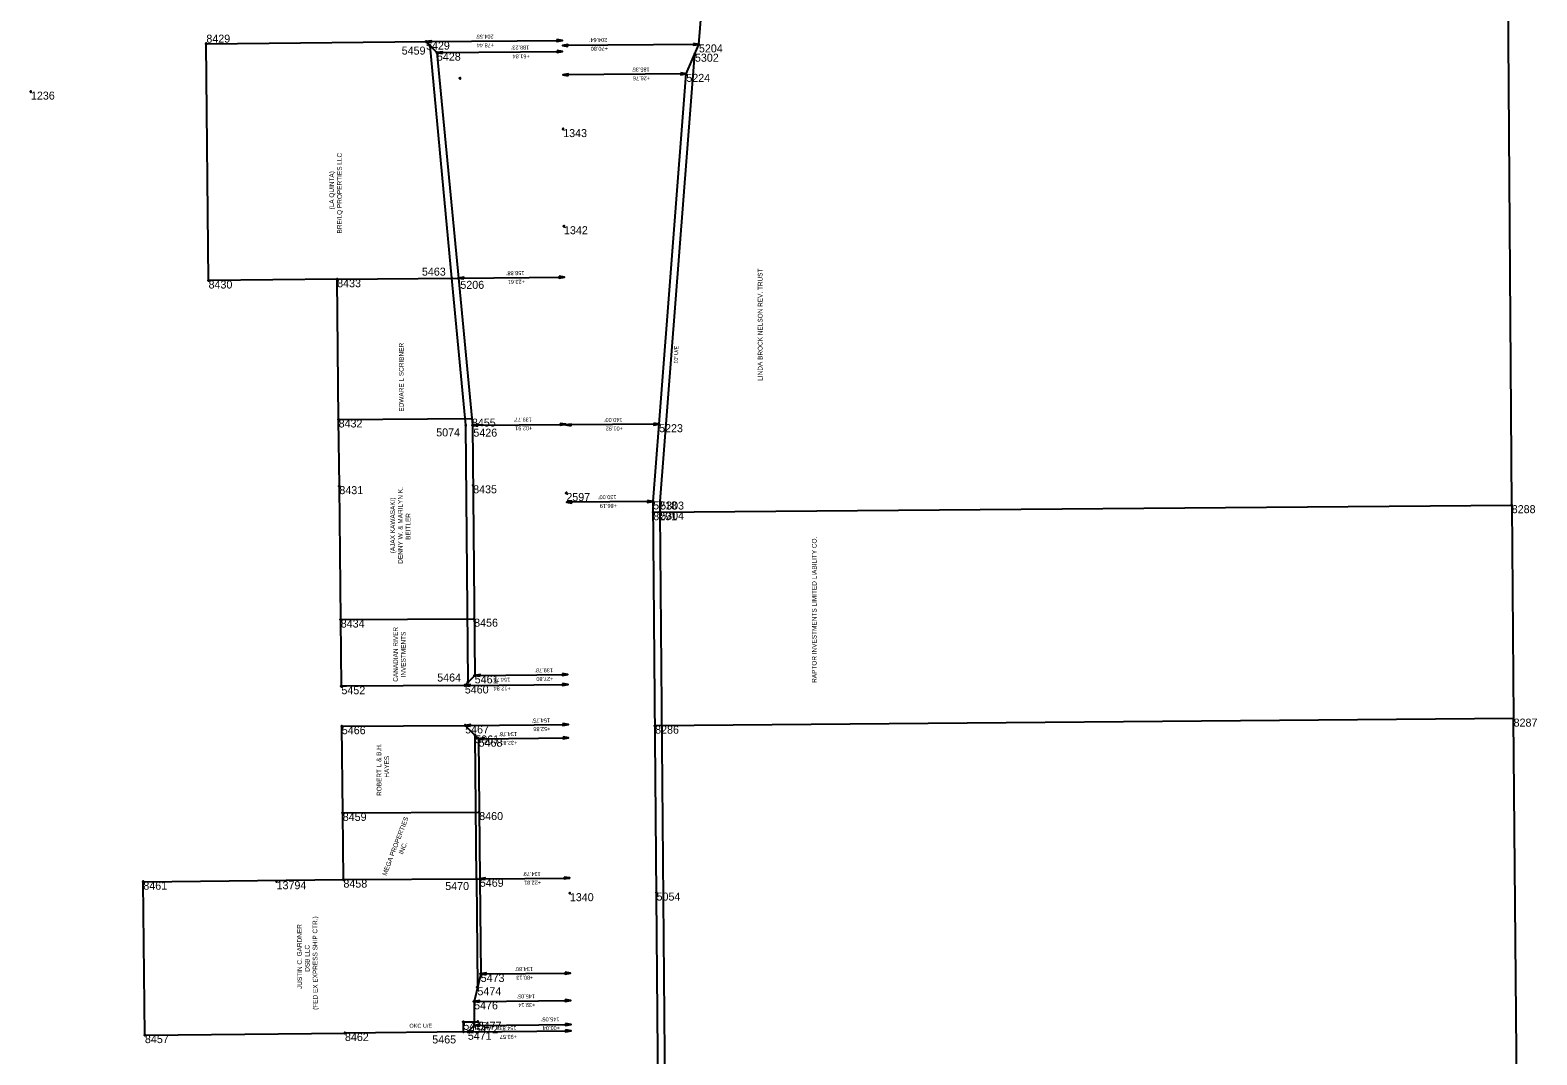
# Model space of a CAD drawing. Extents: x 2145146 to 2158053, y 137507 to 150829.
# Drawn here: x 2150050 to 2152309, y 138777 to 140313 of the extents above; entities that cross this region are included whole.
import ezdxf

# ---------------------------------------------------------------- set-up
doc = ezdxf.new("R2010")
doc.units = 0
for name, color, linetype in [('ALIGN_Cogo Points', 7, 'Continuous'), ('ALIGN_ROW Dimension', 7, 'Continuous'), ('ALIGN_ROW Line', 7, 'Continuous'), ('PLSS_Easement', 7, 'Continuous'), ('PLSS_Property Line', 7, 'Continuous'), ('PLSS_Text', 7, 'Continuous'), ('PLSS_Text_TURNED OFF', 7, 'Continuous')]:
    doc.layers.add(name, color=color, linetype=linetype)

# ---------------------------------------------------------------- blocks, each defined once
blk = doc.blocks.new('Arrowhd')
at = {"layer": 'PLSS_Property Line'}
blk.add_lwpolyline([(0.125, -0.021), (0.125, 0.021), (0, 0)], close=True, dxfattribs=at)

msp = doc.modelspace()

# ---------------------------------------------------------------- linework, layer by layer
at = {"layer": 'ALIGN_Cogo Points'}
for points in [[(2150314.4, 140292.8), (2150314.4, 140294), (2150314.4, 140292.8), (2150313.2, 140292.8), (2150314.4, 140292.8), (2150314.4, 140291.6), (2150314.4, 140292.8), (2150315.6, 140292.8)], [(2150643.8, 140296), (2150643.8, 140297.2), (2150643.8, 140296), (2150642.6, 140296), (2150643.8, 140296), (2150643.8, 140294.8), (2150643.8, 140296), (2150645, 140296)], [(2150649.8, 140289.9), (2150649.8, 140291.1), (2150649.8, 140289.9), (2150648.6, 140289.9), (2150649.8, 140289.9), (2150649.8, 140288.7), (2150649.8, 140289.9), (2150651, 140289.9)], [(2151053, 140291.9), (2151053, 140293.1), (2151053, 140291.9), (2151051.8, 140291.9), (2151053, 140291.9), (2151053, 140290.7), (2151053, 140291.9), (2151054.2, 140291.9)], [(2150660.2, 140279.5), (2150660.2, 140280.7), (2150660.2, 140279.5), (2150659, 140279.5), (2150660.2, 140279.5), (2150660.2, 140278.3), (2150660.2, 140279.5), (2150661.4, 140279.5)], [(2151047, 140277.9), (2151047, 140279.1), (2151047, 140277.9), (2151045.8, 140277.9), (2151047, 140277.9), (2151047, 140276.7), (2151047, 140277.9), (2151048.2, 140277.9)], [(2150694.9, 140241.2), (2150694.9, 140242.4), (2150694.9, 140241.2), (2150693.7, 140241.2), (2150694.9, 140241.2), (2150694.9, 140240), (2150694.9, 140241.2), (2150696.1, 140241.2)], [(2151034.1, 140247.7), (2151034.1, 140248.9), (2151034.1, 140247.7), (2151032.9, 140247.7), (2151034.1, 140247.7), (2151034.1, 140246.5), (2151034.1, 140247.7), (2151035.3, 140247.7)], [(2150051.5, 140221.1), (2150051.5, 140222.3), (2150051.5, 140221.1), (2150050.3, 140221.1), (2150051.5, 140221.1), (2150051.5, 140219.9), (2150051.5, 140221.1), (2150052.7, 140221.1)], [(2150849.5, 140164.9), (2150849.5, 140166.1), (2150849.5, 140164.9), (2150848.3, 140164.9), (2150849.5, 140164.9), (2150849.5, 140163.7), (2150849.5, 140164.9), (2150850.7, 140164.9)], [(2150850.7, 140019.3), (2150850.7, 140020.5), (2150850.7, 140019.3), (2150849.5, 140019.3), (2150850.7, 140019.3), (2150850.7, 140018.1), (2150850.7, 140019.3), (2150851.9, 140019.3)], [(2150317.8, 139937.9), (2150317.8, 139939.1), (2150317.8, 139937.9), (2150316.6, 139937.9), (2150317.8, 139937.9), (2150317.8, 139936.7), (2150317.8, 139937.9), (2150319, 139937.9)], [(2150510.6, 139939.8), (2150510.6, 139941), (2150510.6, 139939.8), (2150509.4, 139939.8), (2150510.6, 139939.8), (2150510.6, 139938.6), (2150510.6, 139939.8), (2150511.8, 139939.8)], [(2150682.5, 139941.4), (2150682.5, 139942.6), (2150682.5, 139941.4), (2150681.3, 139941.4), (2150682.5, 139941.4), (2150682.5, 139940.2), (2150682.5, 139941.4), (2150683.7, 139941.4)], [(2150692.5, 139941.5), (2150692.5, 139942.7), (2150692.5, 139941.5), (2150691.3, 139941.5), (2150692.5, 139941.5), (2150692.5, 139940.3), (2150692.5, 139941.5), (2150693.7, 139941.5)], [(2150512.8, 139729.6), (2150512.8, 139730.8), (2150512.8, 139729.6), (2150511.6, 139729.6), (2150512.8, 139729.6), (2150512.8, 139728.4), (2150512.8, 139729.6), (2150514, 139729.6)], [(2150703.6, 139720.9), (2150703.6, 139722.1), (2150703.6, 139720.9), (2150702.4, 139720.9), (2150703.6, 139720.9), (2150703.6, 139719.7), (2150703.6, 139720.9), (2150704.8, 139720.9)], [(2150712.6, 139730.9), (2150712.6, 139732.1), (2150712.6, 139730.9), (2150711.4, 139730.9), (2150712.6, 139730.9), (2150712.6, 139729.7), (2150712.6, 139730.9), (2150713.8, 139730.9)], [(2150713.6, 139721), (2150713.6, 139722.2), (2150713.6, 139721), (2150712.4, 139721), (2150713.6, 139721), (2150713.6, 139719.8), (2150713.6, 139721), (2150714.8, 139721)], [(2150993.3, 139722.5), (2150993.3, 139723.7), (2150993.3, 139722.5), (2150992.1, 139722.5), (2150993.3, 139722.5), (2150993.3, 139721.3), (2150993.3, 139722.5), (2150994.5, 139722.5)], [(2150513.9, 139629.6), (2150513.9, 139630.8), (2150513.9, 139629.6), (2150512.7, 139629.6), (2150513.9, 139629.6), (2150513.9, 139628.4), (2150513.9, 139629.6), (2150515.1, 139629.6)], [(2150714.5, 139630.9), (2150714.5, 139632.1), (2150714.5, 139630.9), (2150713.3, 139630.9), (2150714.5, 139630.9), (2150714.5, 139629.7), (2150714.5, 139630.9), (2150715.7, 139630.9)], [(2150854.2, 139619.3), (2150854.2, 139620.5), (2150854.2, 139619.3), (2150853, 139619.3), (2150854.2, 139619.3), (2150854.2, 139618.1), (2150854.2, 139619.3), (2150855.4, 139619.3)], [(2150984.4, 139606.7), (2150984.4, 139607.9), (2150984.4, 139606.7), (2150983.2, 139606.7), (2150984.4, 139606.7), (2150984.4, 139605.5), (2150984.4, 139606.7), (2150985.6, 139606.7)], [(2150994.9, 139606.5), (2150994.9, 139607.7), (2150994.9, 139606.5), (2150993.7, 139606.5), (2150994.9, 139606.5), (2150994.9, 139605.3), (2150994.9, 139606.5), (2150996.1, 139606.5)], [(2150984.5, 139590.5), (2150984.5, 139591.7), (2150984.5, 139590.5), (2150983.3, 139590.5), (2150984.5, 139590.5), (2150984.5, 139589.3), (2150984.5, 139590.5), (2150985.7, 139590.5)], [(2150995, 139591.4), (2150995, 139592.6), (2150995, 139591.4), (2150993.8, 139591.4), (2150995, 139591.4), (2150995, 139590.2), (2150995, 139591.4), (2150996.2, 139591.4)], [(2152271.6, 139601.1), (2152271.6, 139602.3), (2152271.6, 139601.1), (2152270.4, 139601.1), (2152271.6, 139601.1), (2152271.6, 139599.9), (2152271.6, 139601.1), (2152272.8, 139601.1)], [(2150516, 139429.6), (2150516, 139430.8), (2150516, 139429.6), (2150514.8, 139429.6), (2150516, 139429.6), (2150516, 139428.4), (2150516, 139429.6), (2150517.2, 139429.6)], [(2150716, 139430.9), (2150716, 139432.1), (2150716, 139430.9), (2150714.8, 139430.9), (2150716, 139430.9), (2150716, 139429.7), (2150716, 139430.9), (2150717.2, 139430.9)], [(2150706.9, 139335.8), (2150706.9, 139337), (2150706.9, 139335.8), (2150705.7, 139335.8), (2150706.9, 139335.8), (2150706.9, 139334.6), (2150706.9, 139335.8), (2150708.1, 139335.8)], [(2150716.8, 139345.9), (2150716.8, 139347.1), (2150716.8, 139345.9), (2150715.6, 139345.9), (2150716.8, 139345.9), (2150716.8, 139344.7), (2150716.8, 139345.9), (2150718, 139345.9)], [(2150517, 139329.6), (2150517, 139330.8), (2150517, 139329.6), (2150515.8, 139329.6), (2150517, 139329.6), (2150517, 139328.4), (2150517, 139329.6), (2150518.2, 139329.6)], [(2150702, 139330.8), (2150702, 139332), (2150702, 139330.8), (2150700.8, 139330.8), (2150702, 139330.8), (2150702, 139329.6), (2150702, 139330.8), (2150703.2, 139330.8)], [(2150517.6, 139269.7), (2150517.6, 139270.9), (2150517.6, 139269.7), (2150516.4, 139269.7), (2150517.6, 139269.7), (2150517.6, 139268.5), (2150517.6, 139269.7), (2150518.8, 139269.7)], [(2150702.5, 139270.9), (2150702.5, 139272.1), (2150702.5, 139270.9), (2150701.3, 139270.9), (2150702.5, 139270.9), (2150702.5, 139269.7), (2150702.5, 139270.9), (2150703.7, 139270.9)], [(2150987.3, 139270.5), (2150987.3, 139271.7), (2150987.3, 139270.5), (2150986.1, 139270.5), (2150987.3, 139270.5), (2150987.3, 139269.3), (2150987.3, 139270.5), (2150988.5, 139270.5)], [(2152274.4, 139281.1), (2152274.4, 139282.3), (2152274.4, 139281.1), (2152273.2, 139281.1), (2152274.4, 139281.1), (2152274.4, 139279.9), (2152274.4, 139281.1), (2152275.6, 139281.1)], [(2150717.7, 139255.9), (2150717.7, 139257.1), (2150717.7, 139255.9), (2150716.5, 139255.9), (2150717.7, 139255.9), (2150717.7, 139254.7), (2150717.7, 139255.9), (2150718.9, 139255.9)], [(2150722.7, 139251), (2150722.7, 139252.2), (2150722.7, 139251), (2150721.5, 139251), (2150722.7, 139251), (2150722.7, 139249.8), (2150722.7, 139251), (2150723.9, 139251)], [(2150519, 139139.7), (2150519, 139140.9), (2150519, 139139.7), (2150517.8, 139139.7), (2150519, 139139.7), (2150519, 139138.5), (2150519, 139139.7), (2150520.2, 139139.7)], [(2150723.6, 139141), (2150723.6, 139142.2), (2150723.6, 139141), (2150722.4, 139141), (2150723.6, 139141), (2150723.6, 139139.8), (2150723.6, 139141), (2150724.8, 139141)], [(2150520, 139039.7), (2150520, 139040.9), (2150520, 139039.7), (2150518.8, 139039.7), (2150520, 139039.7), (2150520, 139038.5), (2150520, 139039.7), (2150521.2, 139039.7)], [(2150719.5, 139041), (2150719.5, 139042.2), (2150719.5, 139041), (2150718.3, 139041), (2150719.5, 139041), (2150719.5, 139039.8), (2150719.5, 139041), (2150720.7, 139041)], [(2150724.5, 139041), (2150724.5, 139042.2), (2150724.5, 139041), (2150723.3, 139041), (2150724.5, 139041), (2150724.5, 139039.8), (2150724.5, 139041), (2150725.7, 139041)], [(2150220, 139036.6), (2150220, 139037.8), (2150220, 139036.6), (2150218.8, 139036.6), (2150220, 139036.6), (2150220, 139035.4), (2150220, 139036.6), (2150221.2, 139036.6)], [(2150419.8, 139037.3), (2150419.8, 139038.5), (2150419.8, 139037.3), (2150418.6, 139037.3), (2150419.8, 139037.3), (2150419.8, 139036.1), (2150419.8, 139037.3), (2150421, 139037.3)], [(2150859.5, 139019.4), (2150859.5, 139020.6), (2150859.5, 139019.4), (2150858.3, 139019.4), (2150859.5, 139019.4), (2150859.5, 139018.2), (2150859.5, 139019.4), (2150860.7, 139019.4)], [(2150989.5, 139020.3), (2150989.5, 139021.5), (2150989.5, 139020.3), (2150988.3, 139020.3), (2150989.5, 139020.3), (2150989.5, 139019.1), (2150989.5, 139020.3), (2150990.7, 139020.3)], [(2150725.8, 138898.3), (2150725.8, 138899.5), (2150725.8, 138898.3), (2150724.6, 138898.3), (2150725.8, 138898.3), (2150725.8, 138897.1), (2150725.8, 138898.3), (2150727, 138898.3)], [(2150720.9, 138878.3), (2150720.9, 138879.5), (2150720.9, 138878.3), (2150719.7, 138878.3), (2150720.9, 138878.3), (2150720.9, 138877.1), (2150720.9, 138878.3), (2150722.1, 138878.3)], [(2150715.9, 138857.2), (2150715.9, 138858.4), (2150715.9, 138857.2), (2150714.7, 138857.2), (2150715.9, 138857.2), (2150715.9, 138856), (2150715.9, 138857.2), (2150717.1, 138857.2)], [(2150699.8, 138826.5), (2150699.8, 138827.7), (2150699.8, 138826.5), (2150698.6, 138826.5), (2150699.8, 138826.5), (2150699.8, 138825.3), (2150699.8, 138826.5), (2150701, 138826.5)], [(2150716.2, 138821.1), (2150716.2, 138822.3), (2150716.2, 138821.1), (2150715, 138821.1), (2150716.2, 138821.1), (2150716.2, 138819.9), (2150716.2, 138821.1), (2150717.4, 138821.1)], [(2150721.3, 138826.7), (2150721.3, 138827.9), (2150721.3, 138826.7), (2150720.1, 138826.7), (2150721.3, 138826.7), (2150721.3, 138825.5), (2150721.3, 138826.7), (2150722.5, 138826.7)], [(2150222.4, 138806.6), (2150222.4, 138807.8), (2150222.4, 138806.6), (2150221.2, 138806.6), (2150222.4, 138806.6), (2150222.4, 138805.4), (2150222.4, 138806.6), (2150223.6, 138806.6)], [(2150522.3, 138809.7), (2150522.3, 138810.9), (2150522.3, 138809.7), (2150521.1, 138809.7), (2150522.3, 138809.7), (2150522.3, 138808.5), (2150522.3, 138809.7), (2150523.5, 138809.7)], [(2150700, 138811.5), (2150700, 138812.7), (2150700, 138811.5), (2150698.8, 138811.5), (2150700, 138811.5), (2150700, 138810.3), (2150700, 138811.5), (2150701.2, 138811.5)], [(2150706.5, 138811.6), (2150706.5, 138812.8), (2150706.5, 138811.6), (2150705.3, 138811.6), (2150706.5, 138811.6), (2150706.5, 138810.4), (2150706.5, 138811.6), (2150707.7, 138811.6)]]:
    msp.add_lwpolyline(points, dxfattribs=at)
at = {"layer": 'ALIGN_ROW Dimension'}
for points in [[(2150643.8, 140296), (2150848.3, 140297.7)], [(2151053, 140291.9), (2150848.4, 140290.1)], [(2150660.2, 140279.5), (2150848.5, 140281.2)], [(2151034.1, 140247.7), (2150848.8, 140246.1)], [(2150692.5, 139941.5), (2150851.4, 139942.9)], [(2150713.6, 139721), (2150853.3, 139722.2)], [(2150993.3, 139722.5), (2150853.4, 139721.3)], [(2150984.4, 139606.6), (2150854.4, 139605.5)], [(2150716.8, 139345.9), (2150856.6, 139347.1)], [(2150702, 139330.8), (2150856.8, 139332.2)], [(2150702.5, 139270.9), (2150857.3, 139272.2)], [(2150722.7, 139251), (2150857.5, 139252.2)], [(2150724.5, 139041), (2150859.3, 139042.1)], [(2150725.8, 138898.3), (2150860.5, 138899.5)], [(2150715.9, 138857.2), (2150860.9, 138858.5)], [(2150716.2, 138821.1), (2150861.2, 138822.4)], [(2150706.5, 138811.6), (2150861.3, 138812.9)]]:
    msp.add_lwpolyline(points, dxfattribs=at)
at = {"layer": 'ALIGN_ROW Line'}
for points in [[(2151467.6, 137757.4), (2151467.4, 137784.4), (2151080.4, 137781.2), (2151054.8, 137833.2), (2151025, 138270.8), (2151014.8, 138420.9), (2151013.1, 138620.9), (2151002.2, 138720.8), (2150992.1, 138720.5), (2150984.4, 139606.7), (2150993.3, 139722.5), (2151034.1, 140247.7), (2151053, 140291.9), (2151058.3, 140359.7), (2151125.2, 141214)], [(2150314.4, 140292.8), (2150643.8, 140296), (2150660.2, 140279.5), (2150692.5, 139941.5), (2150713.6, 139721), (2150716.8, 139345.9), (2150702, 139330.8), (2150517, 139329.6)], [(2150517.6, 139269.7), (2150702.5, 139270.9), (2150722.7, 139251), (2150724.5, 139041), (2150725.8, 138898.3), (2150715.9, 138857.2), (2150716.2, 138821.1), (2150706.5, 138811.6), (2150522.3, 138809.7)]]:
    msp.add_lwpolyline(points, dxfattribs=at)
at = {"layer": 'PLSS_Easement'}
for points in [[(2150706.9, 139335.8), (2150703.6, 139720.9), (2150682.5, 139941.4), (2150649.8, 140289.9)], [(2150995, 139591.4), (2150994.9, 139606.5), (2151047, 140277.9)], [(2151002.2, 138720.8), (2150995, 139590.2)], [(2150719.5, 139041), (2150717.7, 139255.9)], [(2150719.5, 139041), (2150720.9, 138878.3)], [(2150700, 138811.5), (2150699.8, 138826.5), (2150721.3, 138826.7)]]:
    msp.add_lwpolyline(points, dxfattribs=at)
at = {"layer": 'PLSS_Property Line'}
for points in [[(2152271.6, 139601.1), (2152266.1, 140368.7), (2151058.3, 140359.7)], [(2150510.6, 139939.8), (2150317.8, 139937.9), (2150314.4, 140292.8)], [(2150512.8, 139729.6), (2150510.6, 139939.8), (2150692.5, 139941.5)], [(2150516, 139429.6), (2150513.9, 139629.6), (2150512.8, 139729.6), (2150712.6, 139730.9)], [(2150984.5, 139590.5), (2152271.6, 139601.1), (2152274.4, 139281.1)], [(2150517, 139329.6), (2150516, 139429.6), (2150716, 139430.9)], [(2150519, 139139.7), (2150517.6, 139269.7)], [(2152283.1, 138281.1), (2152274.4, 139281.1), (2150987.3, 139270.5)], [(2150520, 139039.7), (2150519, 139139.7), (2150723.6, 139141)], [(2150222.4, 138806.6), (2150220, 139036.6), (2150520, 139039.7), (2150724.5, 139041)], [(2150222.4, 138806.6), (2150522.3, 138809.7)]]:
    msp.add_lwpolyline(points, dxfattribs=at)

# ---------------------------------------------------------------- block references
at = {"layer": 'ALIGN_ROW Dimension', "yscale": 65}
for p, xscale, rotation in [((2150643.7, 140296), 65.00000000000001, 0.7805293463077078), ((2150848.2, 140297.8), 65, 180), ((2150848.4, 140290.1), 65.00000000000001, 0.780529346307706), ((2151053, 140291.9), 65, 180), ((2150660.2, 140279.5), 65.00000000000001, 0.7805293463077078), ((2150848.4, 140281.2), 65, 180), ((2150848.8, 140246.1), 65.00000000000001, 0.7805293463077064), ((2151034.1, 140247.7), 65, 180), ((2150692.5, 139941.5), 65.00000000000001, 0.7805293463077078), ((2150851.4, 139943), 65, 180), ((2150713.6, 139721), 65.00000000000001, 0.7805293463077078), ((2150853.3, 139722.3), 65, 180), ((2150853.4, 139721.3), 65.00000000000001, 0.7805293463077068), ((2150993.3, 139722.5), 65, 180), ((2150854.4, 139605.5), 65.00000000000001, 0.7805293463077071), ((2150984, 139606.7), 65, 180), ((2150716.8, 139345.9), 65.00000000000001, 0.7805293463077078), ((2150856.6, 139347.2), 65, 180), ((2150702, 139330.9), 65.00000000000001, 0.7805293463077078), ((2150856.7, 139332.2), 65, 180), ((2150702.5, 139270.8), 65.00000000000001, 0.7805293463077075), ((2150857.2, 139272.2), 65, 180), ((2150722.7, 139251), 65.00000000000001, 0.7805293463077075), ((2150857.4, 139252.2), 65, 180), ((2150724.6, 139041), 65.00000000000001, 0.7805293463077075), ((2150859.2, 139042.2), 65, 180), ((2150725.8, 138898.3), 65.00000000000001, 0.7805293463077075), ((2150860.5, 138899.5), 65, 180), ((2150715.9, 138857.2), 65.00000000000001, 0.7805293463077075), ((2150860.8, 138858.5), 65, 180), ((2150716.2, 138821.1), 65.00000000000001, 0.7805293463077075), ((2150861.2, 138822.4), 65, 180), ((2150706.5, 138811.6), 65.00000000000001, 0.7805293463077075), ((2150861.2, 138813), 65, 180)]:
    msp.add_blockref('Arrowhd', p, dxfattribs=dict(at, xscale=xscale, rotation=rotation))

# ---------------------------------------------------------------- texts
at = {"layer": 'ALIGN_Cogo Points'}
for s, p in [('8429', (2150314.5, 140294.5)), ('5459', (2150607.4, 140276.6)), ('5429', (2150643.8, 140284)), ('5204', (2151053, 140279.9)), ('5428', (2150660.2, 140267.5)), ('5302', (2151047, 140265.9)), ('5224', (2151034.1, 140235.7)), ('1236', (2150051.5, 140209.1)), ('1343', (2150849.5, 140152.9)), ('1342', (2150850.7, 140007.3)), ('5463', (2150637.7, 139945.2)), ('8430', (2150317.8, 139925.9)), ('8433', (2150510.6, 139927.8)), ('5206', (2150695.3, 139925.4)), ('8432', (2150512.8, 139717.6)), ('8455', (2150712.6, 139718.9)), ('5223', (2150993.3, 139710.5)), ('5074', (2150659.1, 139704.2)), ('5426', (2150714.8, 139703.8)), ('8431', (2150513.9, 139617.6)), ('8435', (2150714.5, 139618.9)), ('2597', (2150854.2, 139607.3)), ('5218', (2150984.4, 139594.7)), ('5303', (2150994.9, 139594.5)), ('8291', (2150984.5, 139578.5)), ('5304', (2150995, 139579.4)), ('8288', (2152271.6, 139589.1)), ('8434', (2150516, 139417.6)), ('8456', (2150716, 139418.9)), ('5464', (2150660.6, 139336.7)), ('5461', (2150716.8, 139333.9)), ('5452', (2150517, 139317.6)), ('5460', (2150702, 139318.8)), ('5466', (2150517.6, 139257.7)), ('5467', (2150702.5, 139258.9)), ('8286', (2150987.3, 139258.5)), ('8287', (2152274.4, 139269.1)), ('5061', (2150717.7, 139243.9)), ('5468', (2150722.7, 139239)), ('8459', (2150519, 139127.7)), ('8460', (2150723.6, 139129)), ('5469', (2150724.5, 139029)), ('8461', (2150220, 139024.6)), ('13794', (2150419.8, 139025.3)), ('8458', (2150520, 139027.7)), ('5470', (2150672.6, 139024.1)), ('1340', (2150859.5, 139007.4)), ('5054', (2150989.5, 139008.3)), ('5473', (2150725.8, 138886.3)), ('5474', (2150720.9, 138866.3)), ('5476', (2150715.9, 138845.2)), ('5475', (2150699.8, 138814.5)), ('5472', (2150716.2, 138809.1)), ('5477', (2150721.3, 138814.7)), ('8457', (2150222.4, 138794.6)), ('8462', (2150522.3, 138797.7)), ('5465', (2150653.2, 138794.1)), ('5471', (2150706.5, 138799.6))]:
    msp.add_text(s, height=12, dxfattribs=at).set_placement(p)
at = {"layer": 'ALIGN_ROW Dimension'}
for s, p in [("204.55'", (2150745.1, 140306.6)), ('+78.44', (2150745.7, 140293.6)), ("188.23'", (2150798.6, 140290.1)), ("204.64'", (2150915.6, 140301.4)), ('+70.80', (2150916.3, 140288.4)), ('+61.84', (2150799.2, 140277)), ("185.35'", (2150979, 140257.2)), ('+26.76', (2150979.7, 140244.2)), ("158.88'", (2150791.3, 139952)), ('+23.61', (2150791.9, 139939)), ("139.77'", (2150802.4, 139732.4)), ('+02.91', (2150803.1, 139719.4)), ("140.00'", (2150938.3, 139732)), ('+01.92', (2150938.9, 139719)), ("130.00'", (2150929.3, 139616.2)), ('+86.19', (2150929.9, 139603.1)), ("154.74'", (2150770, 139342.3)), ("139.78'", (2150834.1, 139356.5)), ('+27.80', (2150834.8, 139343.5)), ('+12.84', (2150770.7, 139329.2)), ("154.75'", (2150829.7, 139281.4)), ('+52.86', (2150830.3, 139268.4)), ("134.78'", (2150780.2, 139260.9)), ('+32.81', (2150780.8, 139247.8)), ("134.79'", (2150815.6, 139051.2)), ('+22.81', (2150816.3, 139038.1)), ("134.80'", (2150804.1, 138908.7)), ('+80.13', (2150804.8, 138895.7)), ("145.05'", (2150807.1, 138867.8)), ('+39.14', (2150807.7, 138854.7)), ("154.83'", (2150779.4, 138820.1)), ("145.05'", (2150843.8, 138833.3)), ('+03.04', (2150844.4, 138820.2)), ('+93.57', (2150780, 138807.1))]:
    msp.add_text(s, height=6, rotation=180.3718, dxfattribs=at).set_placement(p)
at = {"layer": 'PLSS_Text'}
msp.add_text("10' U/E ", height=6, rotation=87.3057, dxfattribs=at).set_placement((2151021.1, 139813))
msp.add_text('OKC U/E', height=6, dxfattribs=at).set_placement((2150618.9, 138817.6))
at = {"layer": 'PLSS_Text_TURNED OFF'}
for s, rotation, p in [('BRE/LQ PROPERTIES LLC', 90, (2150517.5, 140008.4)), ('(LA QUINTA)', 90, (2150505.8, 140044.4)), ('LINDA BROCK NELSON REV. TRUST', 90, (2151148.3, 139787.7)), ('EDWARE L SCRIBNER', 90, (2150610.3, 139741.3)), ('(AJAX KAWASAKI)', 90, (2150597.2, 139528.9)), ('DENNY W. & MARILYN K.', 90, (2150608.8, 139513.2)), ('BEITLER', 90, (2150620.5, 139549)), ('RAPTOR INVESTMENTS LIMITED LIABILITY CO.', 90, (2151229.4, 139334.7)), ('CANADIAN RIVER', 90, (2150601.6, 139336.3)), ('INVESTMENTS', 90, (2150613.3, 139342.8)), ('ROBERT L & B.H.', 90.2855, (2150577, 139165.2)), ('HAYES', 90.2855, (2150588.6, 139192.6)), ('MEGA PROPERTIES', 69.0968, (2150584.4, 139045)), ('INC.', 69.0968, (2150609.1, 139076.9)), ('(FED EX EXPRESS SHIP CTR.)', 90.217, (2150481.3, 138844.5)), ('JUSTIN C. GARDNER', 90.217, (2150457.8, 138875.8)), ('DSB LLC', 90.217, (2150469.3, 138901.6))]:
    msp.add_text(s, height=7, rotation=rotation, dxfattribs=at).set_placement(p)

doc.saveas('drawing.dxf')
